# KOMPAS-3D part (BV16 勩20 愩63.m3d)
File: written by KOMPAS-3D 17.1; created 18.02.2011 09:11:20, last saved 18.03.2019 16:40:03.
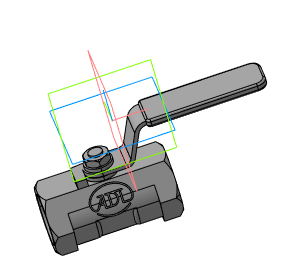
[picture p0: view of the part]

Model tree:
1. Плоскость XY
2. Плоскость ZX
3. Плоскость ZY
4. Ось X
5. Ось Y
6. Ось Z
7. Начало координат
8. Операция без истории:2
